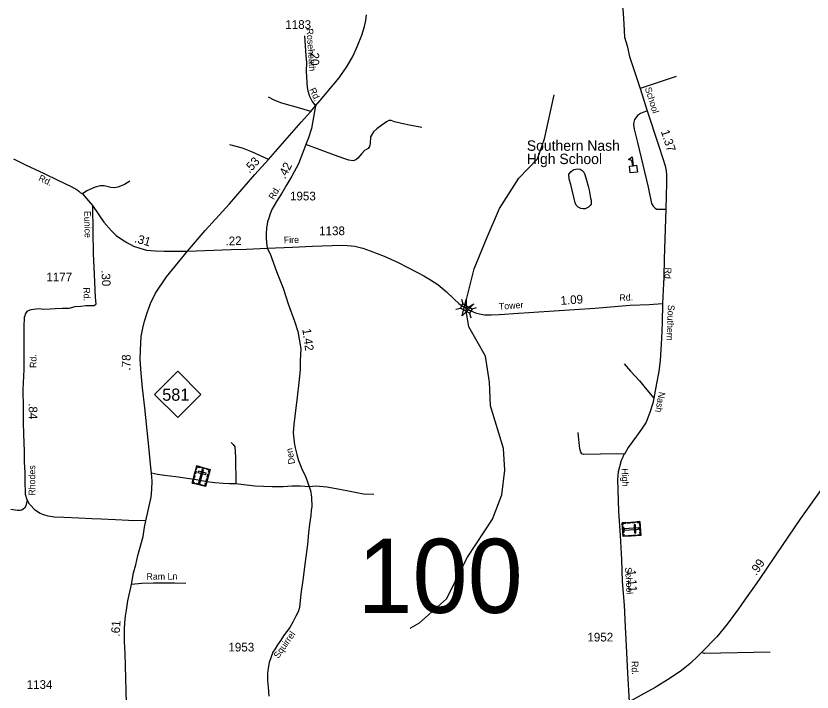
# Model space of a CAD drawing. Extents: x 2220236 to 2384410, y 720751 to 894131.
# Drawn here: x 2261578 to 2273033, y 758435 to 768164 of the extents above; entities that cross this region are included whole.
import ezdxf

# ---------------------------------------------------------------- set-up
doc = ezdxf.new("R2010")
doc.units = 0
doc.layers.add('Default', color=7, linetype='Continuous')

msp = doc.modelspace()

# ---------------------------------------------------------------- linework, layer by layer
at = {"layer": 'Default'}
for p, q in [((2271079, 767293), (2270558, 767120)), ((2267990, 764089), (2268009, 764022)), ((2267908, 763942), (2267974, 763961)), ((2268140, 763948), (2268207, 763966)), ((2268106, 763887), (2268125, 763821))]:
    msp.add_line(p, q, dxfattribs=at)
for points in [[(2270306, 768293), (2270316, 768205), (2270325, 768047), (2270335, 767859), (2270371, 767732), (2270407, 767580), (2270464, 767406), (2270558, 767120), (2270660, 766796), (2270823, 766303), (2270886, 766113), (2270919, 766007), (2270932, 765934), (2270937, 765878), (2270939, 765756), (2270932, 765574), (2270927, 765384), (2270904, 764668), (2270901, 764411), (2270880, 764025)], [(2265889, 766869), (2265983, 766982), (2266050, 767060), (2266231, 767275), (2266345, 767441), (2266428, 767588), (2266494, 767732), (2266553, 767885), (2266592, 768012), (2266614, 768100), (2266623, 768178)], [(2265730, 767875), (2265749, 767590), (2265759, 767497), (2265755, 767359), (2265769, 767134), (2265779, 767084), (2265803, 767009), (2265838, 766932), (2265889, 766869)], [(2267252, 759353), (2267385, 759429), (2267773, 759775), (2268076, 760375), (2268437, 760922), (2268567, 761274), (2268613, 761630), (2268594, 761939), (2268405, 762553), (2268393, 762894), (2268332, 763269), (2268094, 763691), (2268058, 763921), (2268058, 763953), (2268061, 764085), (2268074, 764141), (2268170, 764526), (2268357, 764978), (2268537, 765394), (2268816, 765831), (2269080, 766108), (2269185, 766394), (2269321, 767028)], [(2265823, 766786), (2265678, 766831), (2265402, 766910), (2265295, 766951), (2265213, 766993)], [(2264047, 764780), (2264299, 765077), (2264652, 765462), (2265016, 765883), (2265213, 766100), (2265682, 766633), (2265823, 766786), (2265889, 766869)], [(2265889, 766869), (2265831, 766543), (2265788, 766410), (2265749, 766312), (2265706, 766200), (2265643, 766035), (2265550, 765857), (2265475, 765740), (2265406, 765615), (2265326, 765493), (2265262, 765376), (2265237, 765316), (2265215, 765253), (2265200, 765201), (2265183, 765109), (2265177, 765031), (2265178, 764965), (2265182, 764903), (2265195, 764821)], [(2270660, 766796), (2270565, 766760), (2270521, 766731), (2270495, 766697), (2270480, 766672), (2270470, 766635), (2270464, 766601), (2270472, 766534), (2270521, 766340), (2270599, 766021), (2270675, 765698), (2270724, 765465), (2270745, 765424), (2270776, 765397), (2270799, 765384), (2270927, 765384)], [(2267419, 766558), (2267267, 766589), (2267124, 766616), (2267026, 766638), (2266975, 766658), (2266945, 766658), (2266909, 766641), (2266843, 766592), (2266772, 766538), (2266723, 766494), (2266682, 766423), (2266675, 766328), (2266665, 766284), (2266645, 766257), (2266594, 766228), (2266555, 766184), (2266497, 766116), (2266470, 766094), (2266431, 766079), (2266367, 766089), (2266297, 766111), (2266162, 766160), (2265749, 766312)], [(2265213, 766100), (2264982, 766202), (2264836, 766259), (2264654, 766310)], [(2261542, 766109), (2261718, 766021), (2261984, 765896), (2262179, 765801), (2262372, 765711), (2262457, 765659), (2262484, 765641), (2262504, 765624), (2262534, 765603), (2262679, 765436)], [(2269813, 765712), (2269825, 765655), (2269846, 765539), (2269855, 765513), (2269853, 765455), (2269841, 765435), (2269815, 765413), (2269770, 765390), (2269740, 765390), (2269704, 765394), (2269666, 765411), (2269641, 765443), (2269623, 765475), (2269561, 765738), (2269538, 765816), (2269535, 765886), (2269565, 765926), (2269589, 765946), (2269609, 765956), (2269660, 765965), (2269696, 765959), (2269723, 765941), (2269751, 765916), (2269763, 765882), (2269788, 765802), (2269813, 765712)], [(2263215, 765786), (2263138, 765740), (2263082, 765713), (2263044, 765701), (2262994, 765692), (2262944, 765696), (2262888, 765711), (2262850, 765717), (2262788, 765720), (2262716, 765698), (2262599, 765649), (2262534, 765603)], [(2262679, 765436), (2262684, 765052), (2262691, 764747), (2262702, 764441), (2262717, 764110), (2262730, 764023), (2262724, 764009), (2262698, 763994), (2262586, 763990)], [(2262679, 765436), (2262843, 765196), (2262952, 765070), (2263021, 765006), (2263095, 764951), (2263174, 764904), (2263271, 764851), (2263361, 764821), (2263455, 764795), (2263583, 764782), (2263709, 764777), (2263865, 764777), (2264047, 764780)], [(2265195, 764821), (2265556, 764834), (2265845, 764850), (2266267, 764863), (2266351, 764858), (2266455, 764851), (2266571, 764822), (2266675, 764783), (2266876, 764705), (2267070, 764622), (2267219, 764546), (2267356, 764472), (2267447, 764424), (2267541, 764368), (2267647, 764298), (2267771, 764194), (2267878, 764092), (2267950, 764028), (2268028, 763974), (2268056, 763959)], [(2263445, 760898), (2263522, 761239), (2263533, 761350), (2263536, 761470), (2263529, 761583), (2263513, 761713), (2263495, 761919), (2263432, 762526), (2263401, 762814), (2263378, 763023), (2263367, 763218), (2263369, 763354), (2263380, 763553), (2263403, 763670), (2263429, 763771), (2263465, 763890), (2263513, 764028), (2263587, 764173), (2263746, 764409), (2264047, 764780)], [(2264047, 764780), (2264676, 764801), (2264892, 764808), (2265195, 764821)], [(2265195, 764821), (2265234, 764740), (2265327, 764485), (2265421, 764248), (2265496, 764020), (2265587, 763771), (2265634, 763623), (2265655, 763514), (2265666, 763431), (2265675, 763367), (2265673, 763298), (2265670, 763198), (2265668, 763073), (2265647, 762891), (2265625, 762677), (2265598, 762443), (2265577, 762286), (2265567, 762167), (2265577, 762078), (2265581, 762027), (2265596, 761947), (2265619, 761853), (2265644, 761769), (2265693, 761648), (2265746, 761536), (2265770, 761473), (2265798, 761389), (2265814, 761333), (2265831, 761237), (2265834, 761101), (2265827, 761051), (2265819, 760977), (2265800, 760850), (2265788, 760728), (2265772, 760556), (2265741, 760311), (2265705, 760044), (2265679, 759850), (2265657, 759650), (2265639, 759588), (2265606, 759527), (2265564, 759441), (2265517, 759366), (2265429, 759244), (2265390, 759184), (2265341, 759114), (2265307, 759056), (2265276, 759007), (2265245, 758927), (2265222, 758859), (2265205, 758777), (2265200, 758702), (2265196, 758603), (2265205, 758504), (2265216, 758375)], [(2262586, 763990), (2262510, 763985), (2262425, 763976), (2262339, 763954), (2262246, 763955), (2262141, 763947), (2262071, 763944), (2261975, 763941), (2261907, 763949), (2261793, 763937), (2261754, 763921), (2261733, 763909), (2261716, 763880), (2261703, 763836)], [(2268056, 763959), (2268106, 763930), (2268189, 763893), (2268247, 763875), (2268322, 763862), (2268420, 763864), (2268533, 763867), (2268607, 763872), (2268738, 763880), (2269906, 763961), (2270415, 764000), (2270691, 764012), (2270880, 764025)], [(2270880, 764025), (2270875, 763751), (2270872, 763630), (2270862, 763436), (2270847, 763212), (2270828, 763049), (2270795, 762876), (2270756, 762663), (2270743, 762592), (2270699, 762456), (2270644, 762317), (2270581, 762216), (2270509, 762116), (2270387, 761955), (2270332, 761859), (2270321, 761842), (2270303, 761804), (2270288, 761765), (2270244, 761604), (2270231, 761495), (2270236, 761347), (2270247, 761033), (2270272, 760689), (2270290, 760341), (2270301, 760024), (2270327, 759687), (2270342, 759375), (2270356, 759098), (2270379, 758707), (2270399, 758294)], [(2263445, 760898), (2263196, 760906), (2263011, 760911), (2262804, 760922), (2262669, 760927), (2262484, 760938), (2262268, 760945), (2262126, 760953), (2262043, 760964), (2261979, 760985), (2261928, 761002), (2261861, 761046), (2261773, 761137), (2261741, 761200), (2261718, 761278), (2261714, 761336), (2261709, 761430), (2261710, 761594), (2261703, 761742), (2261700, 761903), (2261690, 762146), (2261689, 762318), (2261689, 762531), (2261684, 762788), (2261695, 763077), (2261697, 763383), (2261698, 763682), (2261703, 763836)], [(2270330, 763158), (2270421, 763052), (2270550, 762914), (2270654, 762784), (2270756, 762663)], [(2270332, 761859), (2270225, 761862), (2269990, 761859), (2269745, 761854), (2269722, 761861), (2269706, 761885), (2269692, 761933), (2269675, 762071), (2269668, 762169)], [(2273900, 762117), (2273776, 762003), (2273579, 761804), (2273435, 761662), (2273296, 761515), (2273178, 761369), (2273059, 761201), (2272866, 760933), (2272513, 760409), (2272363, 760190), (2272228, 759991), (2272062, 759755), (2271973, 759635), (2271812, 759413), (2271662, 759231), (2271443, 759002), (2271398, 758959), (2271277, 758844), (2271156, 758745), (2270989, 758635), (2270773, 758503), (2270574, 758389), (2270399, 758294)], [(2264674, 762028), (2264706, 761995), (2264730, 761963), (2264736, 761813), (2264742, 761429)], [(2264742, 761429), (2264652, 761430), (2264558, 761435), (2264439, 761447), (2264326, 761462), (2264201, 761482), (2264107, 761498), (2263977, 761517), (2263879, 761532), (2263717, 761550), (2263617, 761566), (2263529, 761583)], [(2265798, 761389), (2265673, 761397), (2265548, 761399), (2265424, 761389), (2265265, 761387), (2265016, 761400), (2264820, 761420), (2264742, 761429)], [(2266727, 761279), (2266578, 761283), (2266389, 761319), (2266236, 761352), (2266053, 761381), (2265891, 761396), (2265798, 761389)], [(2261741, 761200), (2261722, 761115), (2261700, 761082), (2261661, 761050), (2261637, 761046), (2261601, 761048), (2261503, 761061)], [(2263167, 757725), (2263173, 757939), (2263176, 758064), (2263168, 758268), (2263166, 758462), (2263161, 758627), (2263157, 758817), (2263149, 758989), (2263138, 759161), (2263138, 759337), (2263145, 759435), (2263154, 759529), (2263171, 759613), (2263190, 759749), (2263240, 759985), (2263272, 760150), (2263303, 760268), (2263332, 760400), (2263407, 760675), (2263429, 760807), (2263445, 760898)], [(2264024, 759998), (2263861, 760004), (2263556, 760001), (2263391, 759996), (2263240, 759985)], [(2272428, 759010), (2271487, 758992), (2271443, 759002)]]:
    msp.add_lwpolyline(points, dxfattribs=at)
for points in [[(2270418, 765904), (2270406, 766001), (2270452, 766007), (2270442, 766082), (2270393, 766100), (2270445, 766136), (2270461, 766008), (2270507, 766014), (2270519, 765917)], [(2268168, 764023), (2267999, 763846), (2268057, 764083), (2268058, 763953)], [(2268009, 764022), (2268141, 763948), (2268106, 763886), (2267974, 763961)], [(2263573, 762717), (2263906, 763050), (2264239, 762717), (2263906, 762384)], [(2264179, 761689), (2264371, 761638), (2264306, 761392), (2264113, 761443)], [(2264168, 761648), (2264179, 761645), (2264187, 761676), (2264226, 761665), (2264229, 761676), (2264179, 761689)], [(2264277, 761633), (2264258, 761638), (2264206, 761442), (2264224, 761437)], [(2264250, 761670), (2264300, 761657), (2264297, 761646), (2264247, 761659)], [(2264360, 761596), (2264349, 761599), (2264357, 761630), (2264318, 761641), (2264321, 761652), (2264371, 761638)], [(2264131, 761511), (2264142, 761553), (2264153, 761550), (2264142, 761508)], [(2264149, 761576), (2264160, 761618), (2264171, 761615), (2264160, 761573)], [(2264201, 761613), (2264196, 761595), (2264310, 761565), (2264314, 761583)], [(2264330, 761529), (2264341, 761571), (2264352, 761568), (2264341, 761526)], [(2264145, 761435), (2264148, 761446), (2264127, 761452), (2264137, 761491), (2264127, 761494), (2264113, 761443)], [(2264172, 761440), (2264254, 761418), (2264251, 761407), (2264169, 761429)], [(2264274, 761401), (2264277, 761412), (2264298, 761406), (2264308, 761445), (2264319, 761442), (2264306, 761392)], [(2264313, 761465), (2264324, 761507), (2264335, 761504), (2264324, 761462)], [(2270556, 760888), (2270570, 760689), (2270316, 760672), (2270302, 760871)], [(2270305, 760838), (2270316, 760839), (2270315, 760861), (2270355, 760863), (2270354, 760874), (2270302, 760871)], [(2270372, 760876), (2270415, 760878), (2270416, 760867), (2270373, 760864)], [(2270439, 760880), (2270482, 760883), (2270483, 760872), (2270440, 760869)], [(2270491, 760843), (2270473, 760841), (2270480, 760724), (2270499, 760725)], [(2270513, 760885), (2270514, 760874), (2270546, 760876), (2270549, 760835), (2270560, 760836), (2270556, 760888)], [(2270318, 760814), (2270323, 760730), (2270312, 760729), (2270306, 760814)], [(2270534, 760777), (2270533, 760796), (2270331, 760782), (2270332, 760764)], [(2270526, 760686), (2270526, 760698), (2270558, 760700), (2270555, 760740), (2270566, 760741), (2270570, 760689)], [(2270561, 760814), (2270565, 760762), (2270553, 760761), (2270550, 760813)], [(2270313, 760705), (2270325, 760706), (2270326, 760684), (2270367, 760687), (2270367, 760676), (2270316, 760672)], [(2270387, 760688), (2270430, 760691), (2270431, 760680), (2270388, 760677)], [(2270453, 760693), (2270496, 760696), (2270497, 760684), (2270453, 760681)]]:
    msp.add_lwpolyline(points, close=True, dxfattribs=at)

# ---------------------------------------------------------------- texts
for s, height, p in [('1183', 125, (2265453, 767977)), ('Southern Nash', 150, (2268929, 766223)), ('High School', 150, (2268929, 766032)), ('1953', 125, (2265521, 765509)), ('1138', 125, (2265940, 765009)), ('1177', 125, (2262015, 764344)), ('581', 175, (2263683, 762627)), ('100', 1066.3, (2266491, 759574)), ('1952', 125, (2269800, 759163)), ('1953', 125, (2264635, 759019)), ('1134', 125, (2261732, 758481))]:
    msp.add_text(s, height=height, dxfattribs=at).set_placement(p)
for s, height, rotation, p in [('Roseheath', 95, 273.8809, (2265758, 767979)), ('.20', 125, 270.5639, (2265815, 767683)), ('Rd.', 95, 294.767, (2265797, 767104)), ('School', 95, 287.2441, (2270626, 767123)), ('1.37', 125, 288.2161, (2270855, 766504)), ('.53', 125, 47.661, (2264939, 765892)), ('.42', 125, 62.7995, (2265450, 765810)), ('Rd.', 95, 334.3938, (2261894, 765799)), ('Rd.', 95, 59.6004, (2265288, 765511)), ('Eunice', 95, 270.8686, (2262561, 765357)), ('.31', 125, 344.5682, (2263274, 764909)), ('.22', 125, 1.7238, (2264595, 764861)), ('Fire', 95, 1.1522, (2265433, 764893)), ('Rd.', 95, 268.0445, (2270915, 764545)), ('.30', 125, 272.6392, (2262807, 764503)), ('Rd.', 95, 270.8686, (2262550, 764258)), ('Rd.', 95, 3.7419, (2270263, 764059)), ('1.09', 125, 4.1051, (2269417, 764005)), ('Tower', 95, 4.1494, (2268530, 763936)), ('Southern', 95, 267.602, (2270960, 764008)), ('1.42', 125, 277.8107, (2265698, 763658)), ('Rd.', 95, 89.7941, (2261873, 763098)), ('.78', 125, 89.3183, (2263226, 763060)), ('Nash', 95, 259.8195, (2270829, 762760)), ('.84', 125, 270.0002, (2261762, 762592)), ('Den', 95, 100.4661, (2265595, 761722)), ('Rhodes', 95, 89.9348, (2261855, 761260)), ('High', 95, 273.1925, (2270290, 761651)), ('.99', 125, 55.7886, (2272229, 760104)), ('Ram Ln', 95, 0.7705, (2263457, 760049)), ('School', 95, 273.1925, (2270342, 760229)), ('1.11', 125, 273.9728, (2270372, 760192)), ('.61', 125, 85.9137, (2263068, 759231)), ('Squirrel', 95, 55.2019, (2265355, 758910)), ('Rd.', 95, 270.8531, (2270437, 758881))]:
    msp.add_text(s, height=height, rotation=rotation, dxfattribs=at).set_placement(p)

doc.saveas('drawing.dxf')
